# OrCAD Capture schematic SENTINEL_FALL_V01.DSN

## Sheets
1 PG5_NRF_SOC
2 PG3_POWER_REG: title: SENTINEL_FALL; rev: V01; note: V01
3 PG4_ESP32
4 PG2_BATTERY_CHARGER: size A3
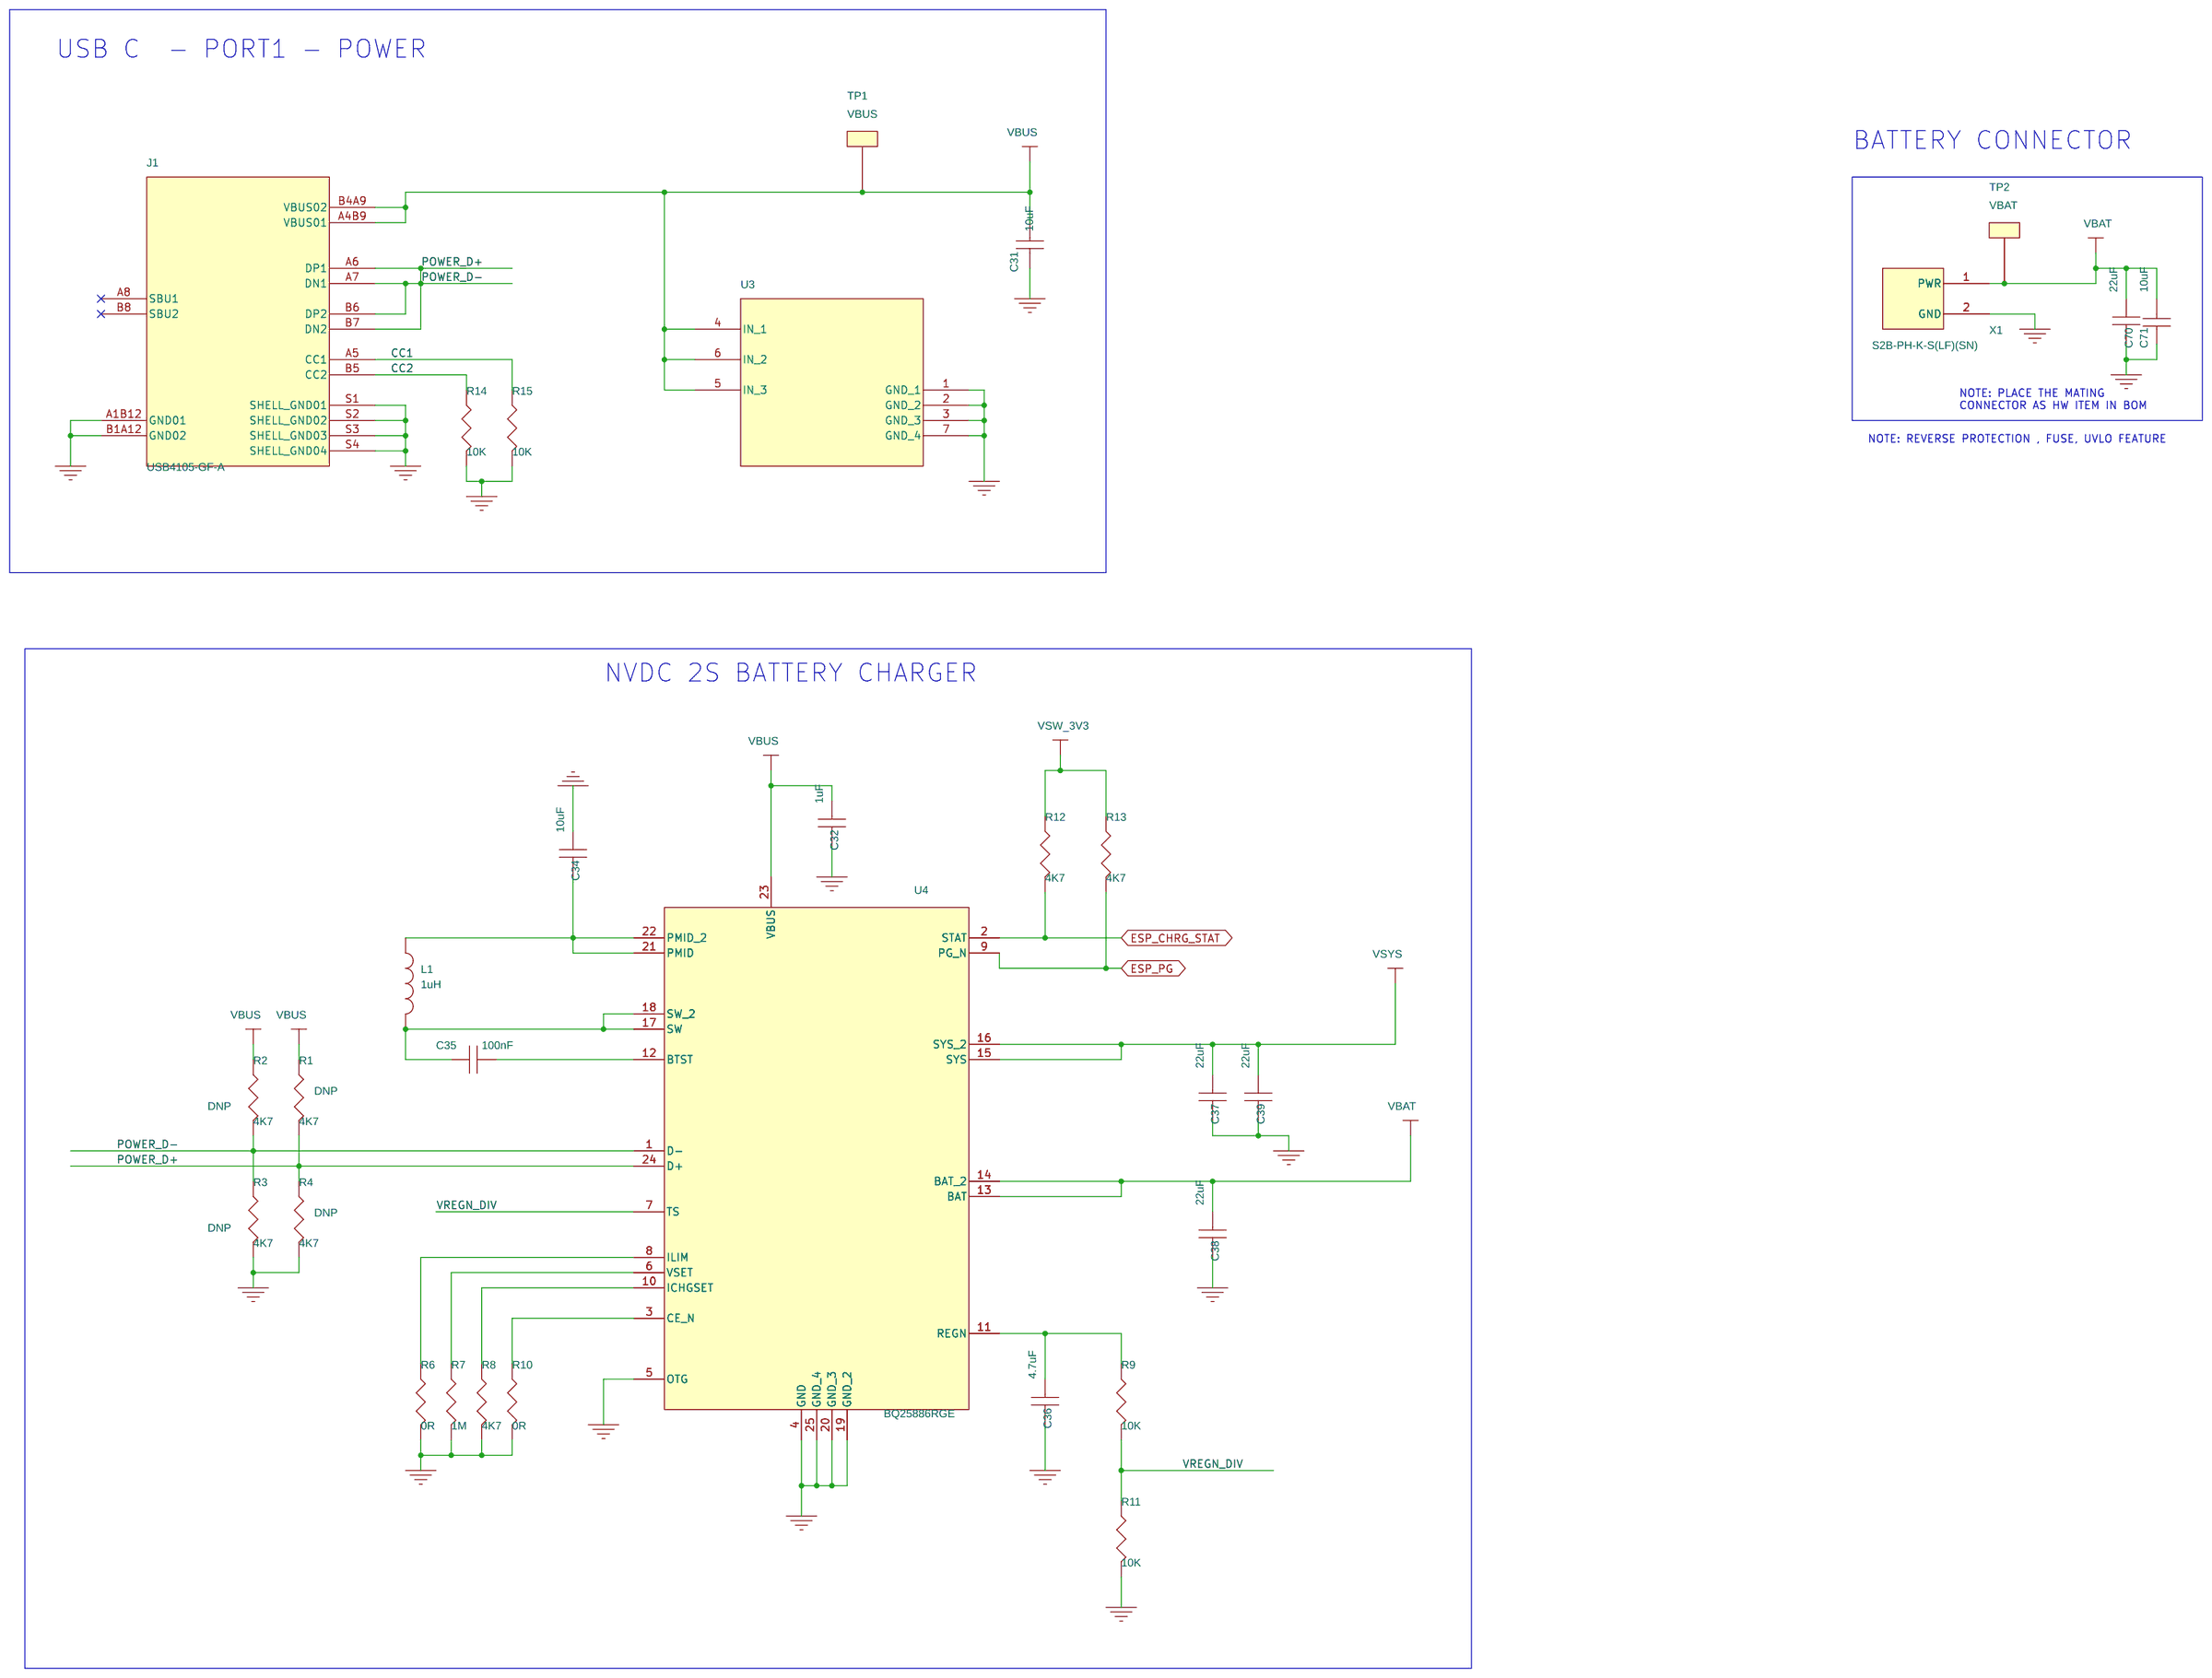
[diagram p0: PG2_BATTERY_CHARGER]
5 PG1_BLOCK_DIAGRAM: title: SENTINEL_FALL; rev: V01; note: V01
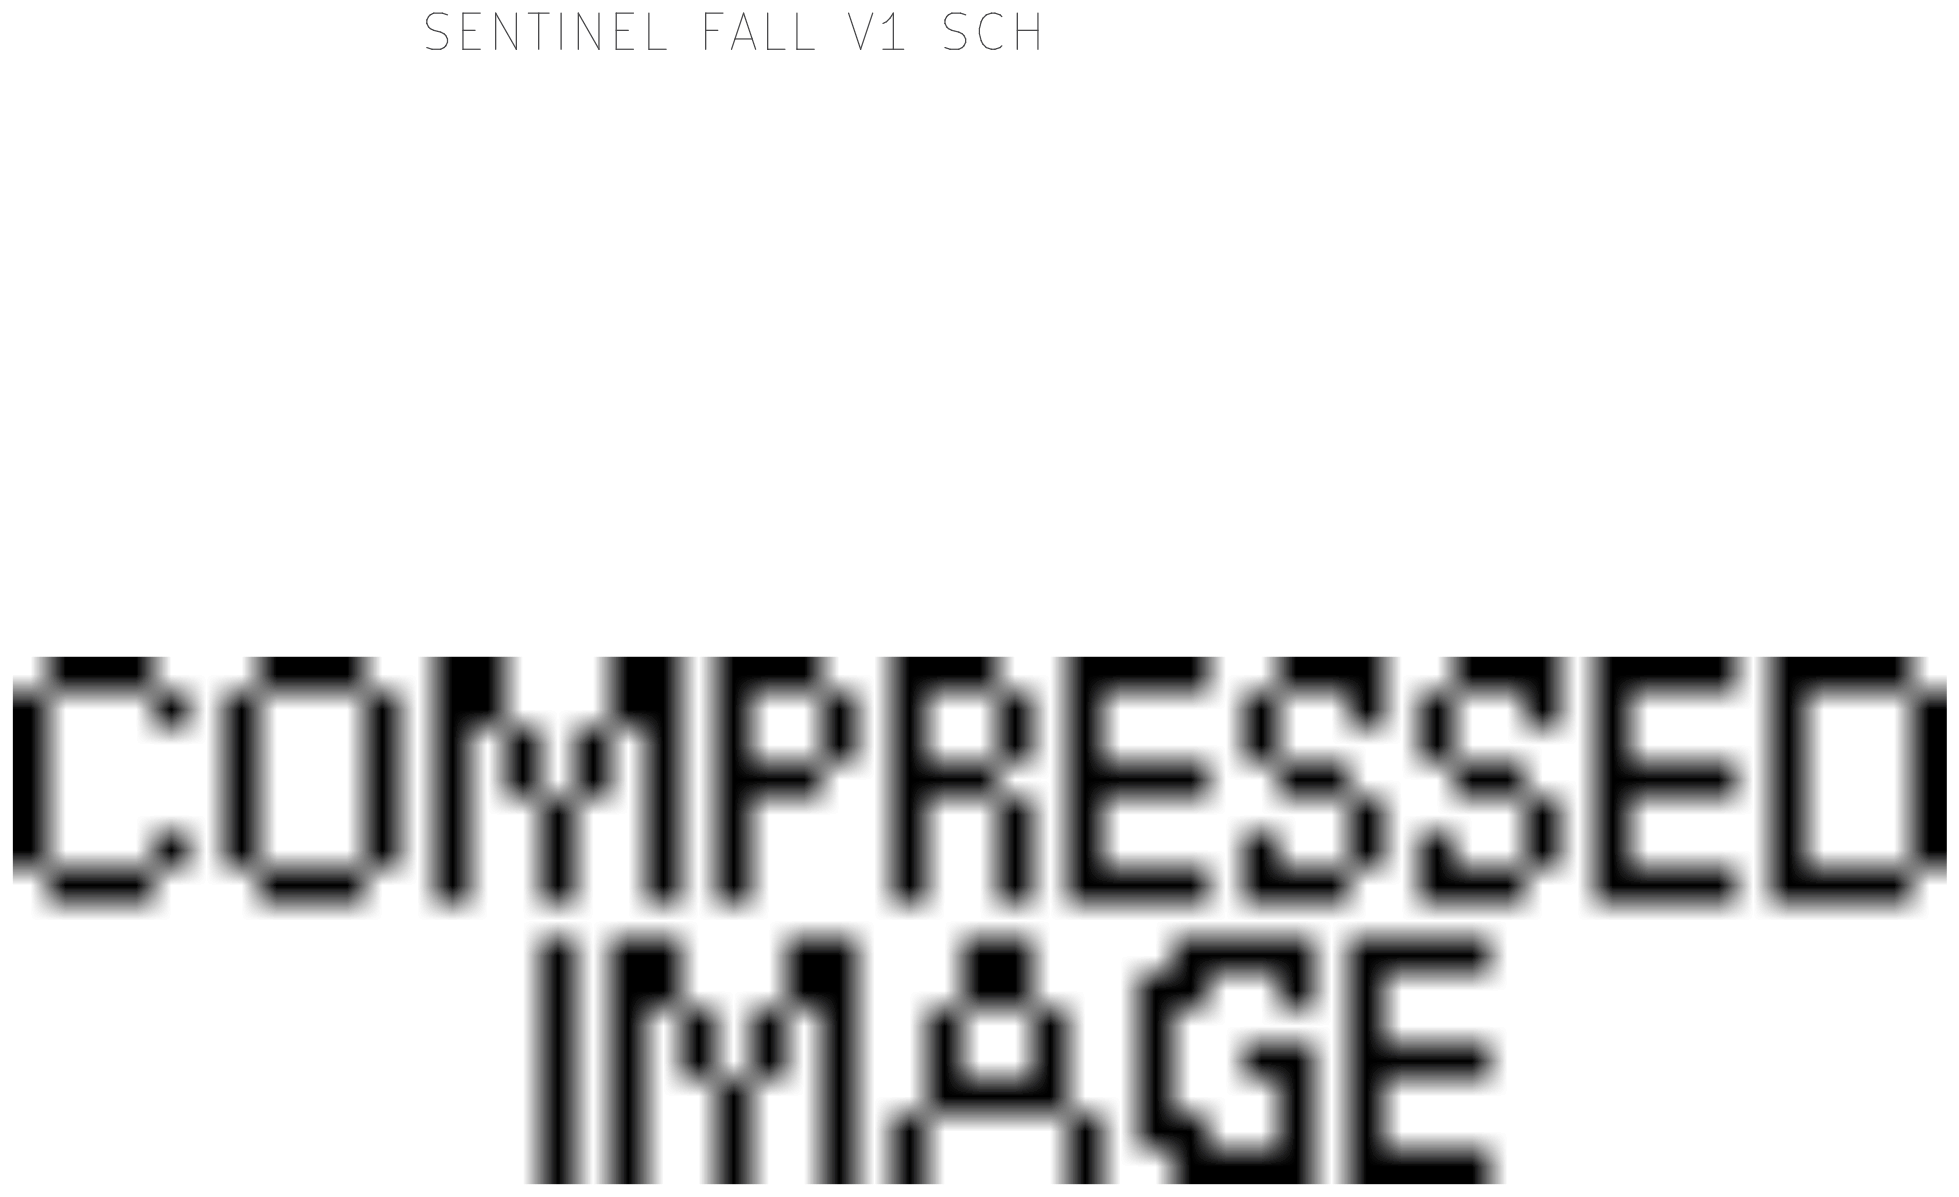
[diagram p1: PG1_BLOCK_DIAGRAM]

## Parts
C31  10uF  [C0805]
C32  1uF  [C0402]
C34  10uF  [C0402]
C35  100nF  [C0402]
C36  4.7uF  [C0402]
C37  22uF  [C0402]
C38  22uF  [C0402]
C39  22uF  [C0402]
C70  22uF  [C0402]
C71  10uF  [C0805]
J1  USB4105-GF-A  [TBD]
L1  1uH  [L0806]
R1  4K7  [R0402]
R2  4K7  [R0402]
R3  4K7  [R0402]
R4  4K7  [R0402]
R6  0R  [R0402]
R7  1M  [R0402]
R8  4K7  [R0402]
R9  10K  [R0402]
R10  0R  [R0402]
R11  10K  [R0402]
R12  4K7  [R0402]
R13  4K7  [R0402]
R14  10K  [R0402]
R15  10K  [R0402]
TP1  VBUS
TP2  VBAT
U3  TVS DIODE  [TBD]
U4  BQ25886RGE  [RGE0024H]
X1  S2B-PH-K-S(LF)(SN)  [JST_RA_2PIN_CONN]

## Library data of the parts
C31 = CAP_CER_10uF_50V_1206_X7R_10P
C32 = CAP_1UF_25V_1206_10P0
C34 = CAP_10UF_50V_X7T_1206
C35 = CAP_100nF_16V_1206_10P0
C36 = CAP_CER_4700nF_50V_X7R_1206
C37-C39 C70 = 4_CAP__22uF_20%_X5R_0805_35VDC
C71 = CAP_NP: Murata, 0805 (2012M) 10uF Multilayer Ceramic Capacitor MLCC 16V dc ±10% , SMD; MFG Name: Murata; MFG Part Number: GRM21BR61C106KE15K
J1 = CONN_USB_USB4105-GF-A
L1 = IND_1uH_11A_1_ukpkg
R1-R4 = RES_4K7_1W4_1P0_1206: BOM NOTE: DNP
R6 R10 = RES_0R0_1W4_1P0_1206
R7 = RES_1M_1W2_0P1_1206
R8 R12 R13 = RES_4K7_1W4_1P0_1206
R9 R11 R14 R15 = RES_10K_1W4_1P0_1206
TP1 TP2 = TEST_POINT_2
U3 = IC_TVS_DIODE
U4 = BQ25886RGER
X1 = HEADER_2_SM_5: JST-PH 2-Pin SMT Right Angle Connector; MFG Name: Adafruit; MFG Part Number: ADA1769

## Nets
GND: C31.2 C32.2 C34.1 C36.2 C37.2 C38.2 C39.2 C70.2 C71.1 J1.A1B12(GND01) J1.B1A12(GND02) J1.S1(SHELL_GND01) J1.S2(SHELL_GND02) J1.S3(SHELL_GND03) J1.S4(SHELL_GND04) R3.2 R4.2 R6.2 R7.2 R8.2 R10.2 R11.2 R14.2 R15.2 U3.1(GND) U3.2(GND) U3.3(GND) U3.7(GND_4) U4.4(GND) U4.5(OTG) U4.19(GND_2) U4.20(GND_3) U4.25(GND_4) X1.2(GND)
VBAT: C38.1 C70.1 C71.2 TP2.1 U4.13(BAT) U4.14(BAT_2) X1.1(PWR)
VBUS: C31.1 C32.1 J1.A4B9(VBUS01) J1.B4A9(VBUS02) R1.1 R2.1 TP1.1 U3.4(IN_1) U3.5(IN_3) U3.6(IN_2) U4.23(VBUS)
CC1: J1.A5(CC1) R15.1
CC2: J1.B5(CC2) R14.1
ESP_CHRG_STAT: R12.2 U4.2(STAT)
ESP_PG: R13.2 U4.9(PG_N)
POWER_D+: J1.A6(DP1) J1.B7(DN2) R1.2 R4.1 U4.24(D+)
POWER_D-: J1.A7(DN1) J1.B6(DP2) R2.2 R3.1 U4.1(D-)
VREGN_DIV: R9.2 R11.1 U4.7(TS)
VSW_3V3: R12.1 R13.1
VSYS: C37.1 C39.1 U4.15(SYS) U4.16(SYS_2)
N489525: C34.2 L1.1 U4.21(PMID) U4.22(PMID_2)
N489966: C35.1 L1.2 U4.17(SW) U4.18(SW_2)
N490283: C35.2 U4.12(BTST)
N491328: R6.1 U4.8(ILIM)
N491337: R7.1 U4.6(VSET)
N491346: R8.1 U4.10(ICHGSET)
N491858: C36.1 R9.1 U4.11(REGN)
N492759: R10.1 U4.3(CE_N)

Not connected (* = marked no-connect by the designer): J1 A8(SBU1)* B8(SBU2)*

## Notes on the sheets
sheet 4
- USB C  - PORT1 - POWER
- BATTERY CONNECTOR
- NOTE: PLACE THE MATING
  CONNECTOR AS HW ITEM IN BOM
- NOTE: REVERSE PROTECTION , FUSE, UVLO FEATURE
- NVDC 2S BATTERY CHARGER
sheet 5
- SENTINEL FALL V1 SCH
